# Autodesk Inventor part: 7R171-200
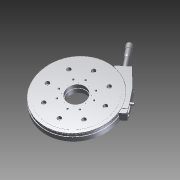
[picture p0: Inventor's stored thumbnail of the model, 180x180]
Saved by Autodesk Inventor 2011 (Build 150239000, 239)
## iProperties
Created: 2012-03
Part Number: 7R171-200
Document SubType Name: Modeling
Designer: vadybininkas6
Density: 1 g/cm^3
Author: vadybininkas6
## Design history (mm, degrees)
feature "Base1"
body "Solid1"
